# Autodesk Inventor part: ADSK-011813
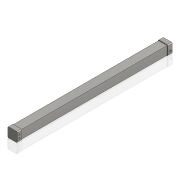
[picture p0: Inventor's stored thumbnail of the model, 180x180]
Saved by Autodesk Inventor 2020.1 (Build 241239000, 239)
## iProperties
Created: 2000-01
Part Number: ADSK-011813
Material: Aluminum
Document SubType Name: Modeling
Designer: mpflueger
Density: 2.71 g/cm^3
Appearance: Steel
Mass: 7082.8 g
Surface Area: 2118.4 cm^2
Volume: 2613.58 cm^3
Control State: 0
Checked Out: False
Master: False
Shininess: 0.0
Length Units: 11269
Angle Units: 11279
Time Units: 11290
Mass Units: 11286
Length Display Precision: 3
Angle Display Precision: 2
Compacted: True
Dimensions: 60x60x952,3 mm
Mass: 15,615 lb
DocNumber: ADSK-011813.ipt
Folder: 01 - Themengebiete\Simplification\01 - Packaging machine\
VDS_Category: 3D Komponenten
Density: 0.0
Volumn: 0.0
Area: 0.0
PropertySet Name: Model Information
Author: mpflueger
Revision Number: -
Title: linear unit
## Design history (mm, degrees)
node "Extrusion1" dims "d2" = 27 (= B), "d3" = 0
node "Chamfer1" dims "d4" = 5, "d5" = 5, "d41" = 45 deg
node "Hole1" dims "d10" = 4.917, "d11" = 9.525, "d12" = 6.35, "d13" = 60 deg, "d14" = 20 (computed from T_deep), "d15" = 118 deg
node "Hole2" dims "d19" = 11.0998, "d20" = 9.525, "d21" = 6.35, "d22" = 60 deg, "d23" = 12.7, "d24" = 118 deg
node "Extrusion2" dims "d30" = 898.3 (= STROKE + 2 x A - 2 x B), "d31" = 0
workplane "Work Plane1"
node "Mirror1"
node "Hole3" dims "d35" = 11.0998, "d36" = 4, "d37" = 2, "d38" = 60 deg, "d39" = 12.7, "d40" = 118 deg
node "Solide1"
node "Corps solides"
node "Corps surfaciques"
sketch "Sketch1"
  geometry: L1 (-30, -30)-(30, -30); L2 (30, -30)-(30, 30); L3 (30, 30)-(-30, 30); L4 (-30, 30)-(-30, -30); L5 (0, 30)-(0, -30); L6 (-30, 0)-(30, 0)
  constraints: 12 end point, 4 midpoint, 2 parallel, 1 horizontal, 1 perpendicular
  dimensions: "d0" = 30 distance between parallel lines of L3 L6 (= 0.5 x R1); "d1" = 30 distance between parallel lines of L4 L5 (= 0.5 x R)
sketch "Sketch2"
  geometry: L1 (25, 30)-(-25, 30) reference; L2 (-25, -30)-(25, -30) reference; L3 (0, -30)-(0, 30); 4 further points
  constraints: 2 end point, 2 horizontal alignment, 2 midpoint, 2 vertical alignment
  dimensions: "d6" = 6.5 distance from line of point (-23.5, -23.5) L2 (= S1); "d7" = 47 distance of point (-23.5, 23.5) point (-23.5, -23.5) (= S); "d8" = 23.5 distance from line of point (-23.5, -23.5) L3 (= 0.5 x S); "d9" = 23.5 distance from line of point (23.5, -23.5) L3 (= 0.5 x S)
sketch "Sketch3"
  geometry: L1 (0, 0)-(0, 50) reference; L2 (27, 55)-(0, 55) reference; L3 (0, -5)-(27, -5) reference; 2 further points
  constraints: 1 vertical alignment
  dimensions: "d16" = 20 distance from line of point (10.5, 15) L3 (= Z); "d17" = 40 distance from line of point (10.5, 35) L3 (= w); "d18" = 10.5 distance from line of point (10.5, 35) L1 (= C)
sketch "Sketch4"
  geometry: L1 (-30, -25)-(-30, 25) reference; L2 (-25, 30)-(25, 30) reference; L3 (-26, 26)-(26, 26); L4 (26, 26)-(26, -26); L5 (26, -26)-(-26, -26); L6 (-26, -26)-(-26, 26); L7 (0, 30)-(0, 26); L8 (-30, 0)-(-26, 0)
  constraints: 12 end point, 4 midpoint, 2 parallel, 1 horizontal, 1 perpendicular
  dimensions: "d28" = 26 distance between parallel lines of L6 L7 (= 0.5 x O1); "d29" = 26 distance between parallel lines of L3 L8 (= 0.5 x O)
sketch "Sketch5"
  geometry: L1 (0, 0)-(0, 50) reference; L2 (-27, -5)-(0, -5) reference; 1 further point
  dimensions: "d33" = 20 distance from line of point (-10.5, 15) L2 (= Z); "d34" = 10.5 distance from line of point (-10.5, 15) L1 (= C)
other parameters: "B" = 27 [user parameter; used in 2 equation terms], "C" = 10.5 [user parameter; used in 2 equation terms], "O" = 52 [user parameter; used in 1 equation term], "O1" = 52 [user parameter; used in 1 equation term], "S" = 47 [user parameter; used in 3 equation terms], "S1" = 6.5 [user parameter; used in 1 equation term], "T_deep" = 15 [user parameter; used in 1 equation term], "w" = 40 [user parameter; used in 1 equation term], "Z" = 20 [user parameter; used in 2 equation terms], "STROKE" = 712.3 [user parameter; used in 2 equation terms], "d32" = -476.15 (= -0.5 x STROKE - A)
